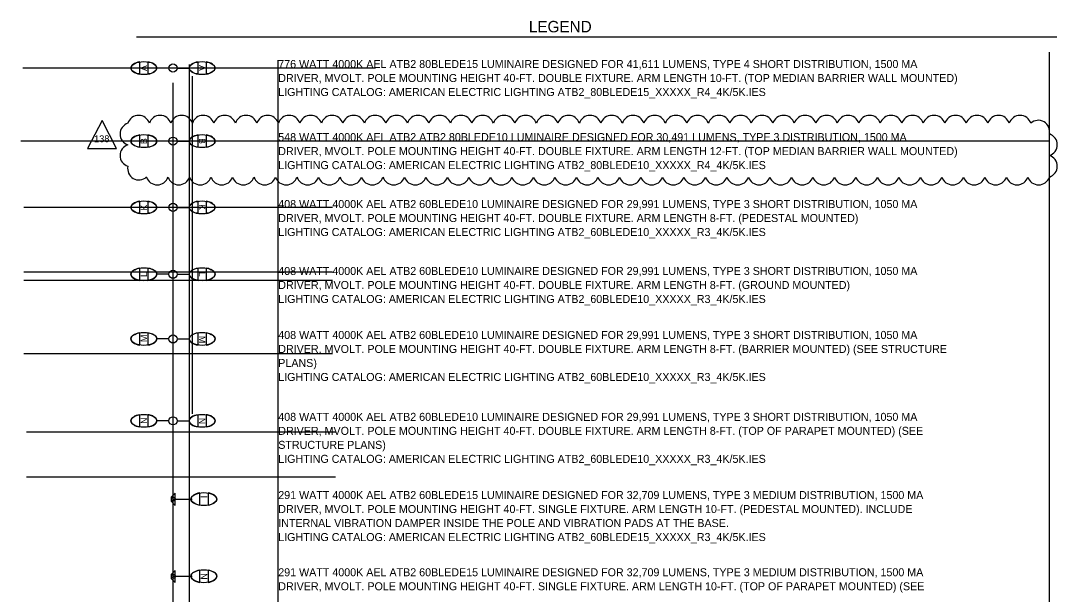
# Model space of a CAD drawing. Extents: x -0.6 to 15.1, y -0.9 to 9.2.
# Drawn here: x 0.27 to 9.34, y 4.17 to 9.19 of the extents above; entities that cross this region are included whole.
import ezdxf

# ---------------------------------------------------------------- set-up
doc = ezdxf.new("R2010")
doc.units = 0
for name, color, linetype in [('ActivePointCell_dp', 7, 'Continuous'), ('Cloud_dp', 7, 'Continuous'), ('PoleLight', 7, 'Continuous'), ('TextLabel', 7, 'Continuous'), ('TextMisc', 7, 'Continuous')]:
    doc.layers.add(name, color=color, linetype=linetype)

msp = doc.modelspace()

# ---------------------------------------------------------------- linework, layer by layer
at = {"layer": 'ActivePointCell_dp'}
for p, q in [((9.2686, -0.1347), (9.2686, 8.9112)), ((1.7419, 8.8041), (1.7419, 0.0422)), ((2.5213, -0.1347), (2.5213, 8.8406)), ((3.3736, 8.7727), (0.2875, 8.7727)), ((1.6003, 8.6424), (1.6003, 0.0422)), ((1.7686, 8.7005), (1.7686, 5.7492)), ((9.2686, 8.1335), (0.268, 8.1335)), ((2.9972, 7.554), (0.2951, 7.554)), ((2.9972, 6.9883), (0.2951, 6.9883)), ((2.9972, 6.913), (0.2951, 6.913)), ((2.9972, 6.272), (0.2951, 6.272)), ((3.0219, 5.588), (0.3198, 5.588)), ((3.0219, 5.1954), (0.3198, 5.1954))]:
    msp.add_line(p, q, dxfattribs=at)
at = {"layer": 'Cloud_dp'}
msp.add_lwpolyline([(0.98, 8.3128), (0.8533, 8.0688), (1.1068, 8.0688)], close=True, dxfattribs=at)
for centre, radius, start, end in [((1.2998, 8.2598), 0.0986, 17.5, 162.5), ((1.4878, 8.2598), 0.0986, 17.5, 162.5), ((1.6759, 8.2598), 0.0986, 17.5, 162.5), ((1.864, 8.2598), 0.0986, 17.5, 162.5), ((2.0521, 8.2598), 0.0986, 17.5, 162.5), ((2.2402, 8.2598), 0.0986, 17.5, 162.5), ((2.4283, 8.2598), 0.0986, 17.5, 162.5), ((2.6164, 8.2598), 0.0986, 17.5, 162.5), ((2.8045, 8.2598), 0.0986, 17.5, 162.5), ((2.9926, 8.2598), 0.0986, 17.5, 162.5), ((3.1807, 8.2598), 0.0986, 17.5, 162.5), ((3.3688, 8.2598), 0.0986, 17.5, 162.5), ((3.5569, 8.2598), 0.0986, 17.5, 162.5), ((3.745, 8.2598), 0.0986, 17.5, 162.5), ((3.9331, 8.2598), 0.0986, 17.5, 162.5), ((4.1212, 8.2598), 0.0986, 17.5, 162.5), ((4.3093, 8.2598), 0.0986, 17.5, 162.5), ((4.4974, 8.2598), 0.0986, 17.5, 162.5), ((4.6855, 8.2598), 0.0986, 17.5, 162.5), ((4.8736, 8.2598), 0.0986, 17.5, 162.5), ((5.0616, 8.2598), 0.0986, 17.5, 162.5), ((5.2497, 8.2598), 0.0986, 17.5, 162.5), ((5.4378, 8.2598), 0.0986, 17.5, 162.5), ((5.6259, 8.2598), 0.0986, 17.5, 162.5), ((5.814, 8.2598), 0.0986, 17.5, 162.5), ((6.0021, 8.2598), 0.0986, 17.5, 162.5), ((6.1902, 8.2598), 0.0986, 17.5, 162.5), ((6.3783, 8.2598), 0.0986, 17.5, 162.5), ((6.5664, 8.2598), 0.0986, 17.5, 162.5), ((6.7545, 8.2598), 0.0986, 17.5, 162.5), ((6.9426, 8.2598), 0.0986, 17.5, 162.5), ((7.1307, 8.2598), 0.0986, 17.5, 162.5), ((7.3188, 8.2598), 0.0986, 17.5, 162.5), ((7.5069, 8.2598), 0.0986, 17.5, 162.5), ((7.695, 8.2598), 0.0986, 17.5, 162.5), ((7.8831, 8.2598), 0.0986, 17.5, 162.5), ((8.0712, 8.2598), 0.0986, 17.5, 162.5), ((8.2593, 8.2598), 0.0986, 17.5, 162.5), ((8.4473, 8.2598), 0.0986, 17.5, 162.5), ((8.6354, 8.2598), 0.0986, 17.5, 162.5), ((8.8235, 8.2598), 0.0986, 17.5, 162.5), ((9.0116, 8.2598), 0.0986, 17.5, 162.5), ((1.2354, 8.1954), 0.0986, 107.5, 252.5), ((9.1723, 8.2169), 0.0985, 347.55602, 132.55602), ((9.2389, 8.1016), 0.0986, 287.5, 72.5), ((1.2354, 8.0074), 0.0986, 107.5, 252.5), ((9.2389, 7.9135), 0.0986, 287.5, 72.5), ((1.3019, 7.8921), 0.0985, 167.55602, 312.55602), ((1.4626, 7.8491), 0.0986, 197.5, 342.5), ((1.6507, 7.8491), 0.0986, 197.5, 342.5), ((1.8388, 7.8491), 0.0986, 197.5, 342.5), ((2.0269, 7.8491), 0.0986, 197.5, 342.5), ((2.215, 7.8491), 0.0986, 197.5, 342.5), ((2.4031, 7.8491), 0.0986, 197.5, 342.5), ((2.5912, 7.8491), 0.0986, 197.5, 342.5), ((2.7793, 7.8491), 0.0986, 197.5, 342.5), ((2.9674, 7.8491), 0.0986, 197.5, 342.5), ((3.1555, 7.8491), 0.0986, 197.5, 342.5), ((3.3436, 7.8491), 0.0986, 197.5, 342.5), ((3.5317, 7.8491), 0.0986, 197.5, 342.5), ((3.7198, 7.8491), 0.0986, 197.5, 342.5), ((3.9079, 7.8491), 0.0986, 197.5, 342.5), ((4.096, 7.8491), 0.0986, 197.5, 342.5), ((4.2841, 7.8491), 0.0986, 197.5, 342.5), ((4.4721, 7.8491), 0.0986, 197.5, 342.5), ((4.6602, 7.8491), 0.0986, 197.5, 342.5), ((4.8483, 7.8491), 0.0986, 197.5, 342.5), ((5.0364, 7.8491), 0.0986, 197.5, 342.5), ((5.2245, 7.8491), 0.0986, 197.5, 342.5), ((5.4126, 7.8491), 0.0986, 197.5, 342.5), ((5.6007, 7.8491), 0.0986, 197.5, 342.5), ((5.7888, 7.8491), 0.0986, 197.5, 342.5), ((5.9769, 7.8491), 0.0986, 197.5, 342.5), ((6.165, 7.8491), 0.0986, 197.5, 342.5), ((6.3531, 7.8491), 0.0986, 197.5, 342.5), ((6.5412, 7.8491), 0.0986, 197.5, 342.5), ((6.7293, 7.8491), 0.0986, 197.5, 342.5), ((6.9174, 7.8491), 0.0986, 197.5, 342.5), ((7.1055, 7.8491), 0.0986, 197.5, 342.5), ((7.2936, 7.8491), 0.0986, 197.5, 342.5), ((7.4817, 7.8491), 0.0986, 197.5, 342.5), ((7.6698, 7.8491), 0.0986, 197.5, 342.5), ((7.8579, 7.8491), 0.0986, 197.5, 342.5), ((8.0459, 7.8491), 0.0986, 197.5, 342.5), ((8.234, 7.8491), 0.0986, 197.5, 342.5), ((8.4221, 7.8491), 0.0986, 197.5, 342.5), ((8.6102, 7.8491), 0.0986, 197.5, 342.5), ((8.7983, 7.8491), 0.0986, 197.5, 342.5), ((8.9864, 7.8491), 0.0986, 197.5, 342.5), ((9.1745, 7.8491), 0.0986, 197.5, 342.5)]:
    msp.add_arc(centre, radius, start, end, dxfattribs=at)
at = {"layer": 'PoleLight'}
for p, q in [((1.3097, 8.719), (1.3097, 8.8264)), ((1.3812, 8.8264), (1.3812, 8.719)), ((1.8194, 8.719), (1.8194, 8.8264)), ((1.8909, 8.8264), (1.8909, 8.719)), ((1.5649, 8.7727), (1.4587, 8.7727)), ((1.6357, 8.7727), (1.7419, 8.7727)), ((1.3097, 8.0797), (1.3097, 8.1872)), ((1.3812, 8.1872), (1.3812, 8.0797)), ((1.8194, 8.0797), (1.8194, 8.1872)), ((1.8909, 8.1872), (1.8909, 8.0797)), ((1.5649, 8.1335), (1.4587, 8.1335)), ((1.6357, 8.1335), (1.7419, 8.1335)), ((1.3097, 7.5003), (1.3097, 7.6078)), ((1.3812, 7.6078), (1.3812, 7.5003)), ((1.5649, 7.554), (1.4587, 7.554)), ((1.6357, 7.554), (1.7419, 7.554)), ((1.8194, 7.5003), (1.8194, 7.6078)), ((1.8909, 7.6078), (1.8909, 7.5003)), ((1.3097, 6.9149), (1.3097, 7.0224)), ((1.3812, 7.0224), (1.3812, 6.9149)), ((1.8194, 6.9149), (1.8194, 7.0224)), ((1.8909, 7.0224), (1.8909, 6.9149)), ((1.5649, 6.9686), (1.4587, 6.9686)), ((1.6357, 6.9686), (1.7419, 6.9686)), ((1.3097, 6.3491), (1.3097, 6.4566)), ((1.3812, 6.4566), (1.3812, 6.3491)), ((1.8194, 6.3491), (1.8194, 6.4566)), ((1.8909, 6.4566), (1.8909, 6.3491)), ((1.5649, 6.4029), (1.4587, 6.4029)), ((1.6357, 6.4029), (1.7419, 6.4029)), ((1.3097, 5.6329), (1.3097, 5.7404)), ((1.3812, 5.7404), (1.3812, 5.6329)), ((1.8194, 5.6329), (1.8194, 5.7404)), ((1.8909, 5.7404), (1.8909, 5.6329)), ((1.5649, 5.6866), (1.4587, 5.6866)), ((1.6357, 5.6866), (1.7419, 5.6866)), ((1.6003, 5.0026), (1.7693, 5.0026)), ((1.8352, 4.9489), (1.8352, 5.0564)), ((1.9067, 5.0564), (1.9067, 4.9489)), ((1.8352, 4.2734), (1.8352, 4.3809)), ((1.9067, 4.3809), (1.9067, 4.2734)), ((1.6003, 4.3271), (1.7693, 4.3271))]:
    msp.add_line(p, q, dxfattribs=at)
for points in [[(1.5845, 5.0185), (1.5846, 4.9828), (1.6202, 4.947), (1.6202, 5.0543)], [(1.5845, 4.3431), (1.5846, 4.3073), (1.6202, 4.2716), (1.6202, 4.3788)]]:
    msp.add_lwpolyline(points, close=True, dxfattribs=at)
for centre, radius in [((1.6003, 8.7727), 0.0354), ((1.6003, 8.7727), 0.0354), ((1.6003, 8.1335), 0.0354), ((1.6003, 8.1335), 0.0354), ((1.6003, 7.554), 0.0354), ((1.6003, 7.554), 0.0354), ((1.6003, 6.9686), 0.0354), ((1.6003, 6.9686), 0.0354), ((1.6003, 6.4029), 0.0354), ((1.6003, 6.4029), 0.0354), ((1.6003, 5.6866), 0.0354), ((1.6003, 5.6866), 0.0354), ((1.6036, 5.0024), 0.0163), ((1.6036, 4.3269), 0.0163)]:
    msp.add_circle(centre, radius, dxfattribs=at)
for centre, major_axis in [((1.3455, 8.7727), (0.1133, 0)), ((1.8551, 8.7727), (0.1133, 0)), ((1.3455, 8.1335), (0.1133, 0)), ((1.8551, 8.1335), (0.1133, 0)), ((1.3455, 7.554), (0.1133, 0)), ((1.8551, 7.554), (0.1133, 0)), ((1.3455, 6.9686), (0.1133, 0)), ((1.8551, 6.9686), (0.1133, 0)), ((1.3455, 6.4029), (0.1133, 0)), ((1.8551, 6.4029), (0.1133, 0)), ((1.3455, 5.6866), (0.1133, 0)), ((1.8551, 5.6866), (0.1133, 0)), ((1.8709, 5.0026), (-0.1133, 0)), ((1.8709, 4.3271), (-0.1133, 0))]:
    msp.add_ellipse(centre, major_axis=major_axis, ratio=0.5, dxfattribs=at)
for centre, major_axis, start_param, end_param in [((1.3455, 8.7727), (0.1133, 0), 1.891945, 4.391241), ((1.3455, 8.7727), (0.1133, 0), 0.847605, 1.249648), ((1.3455, 8.7727), (0.1133, 0), 0, 0.847605), ((1.8551, 8.7727), (0.1133, 0), 1.891945, 4.391241), ((1.8551, 8.7727), (0.1133, 0), 0.847605, 1.249648), ((1.8551, 8.7727), (0.1133, 0), 0, 0.847605), ((1.3455, 8.7727), (0.1133, 0), 5.033538, 6.283185), ((1.8551, 8.7727), (0.1133, 0), 5.033538, 6.283185), ((1.3455, 8.1335), (0.1133, 0), 1.891945, 4.391241), ((1.3455, 8.1335), (0.1133, 0), 0.847605, 1.249648), ((1.3455, 8.1335), (0.1133, 0), 0, 0.847605), ((1.8551, 8.1335), (0.1133, 0), 1.891945, 4.391241), ((1.8551, 8.1335), (0.1133, 0), 0.847605, 1.249648), ((1.8551, 8.1335), (0.1133, 0), 0, 0.847605), ((1.3455, 8.1335), (0.1133, 0), 5.033538, 6.283185), ((1.8551, 8.1335), (0.1133, 0), 5.033538, 6.283185), ((1.3455, 7.554), (0.1133, 0), 1.891945, 4.391241), ((1.3455, 7.554), (0.1133, 0), 0.847605, 1.249648), ((1.3455, 7.554), (0.1133, 0), 5.033538, 6.283185), ((1.3455, 7.554), (0.1133, 0), 0, 0.847605), ((1.8551, 7.554), (0.1133, 0), 1.891945, 4.391241), ((1.8551, 7.554), (0.1133, 0), 0.847605, 1.249648), ((1.8551, 7.554), (0.1133, 0), 5.033538, 6.283185), ((1.8551, 7.554), (0.1133, 0), 0, 0.847605), ((1.3455, 6.9686), (0.1133, 0), 1.891945, 4.391241), ((1.3455, 6.9686), (0.1133, 0), 0.847605, 1.249648), ((1.3455, 6.9686), (0.1133, 0), 0, 0.847605), ((1.8551, 6.9686), (0.1133, 0), 1.891945, 4.391241), ((1.8551, 6.9686), (0.1133, 0), 0.847605, 1.249648), ((1.8551, 6.9686), (0.1133, 0), 0, 0.847605), ((1.3455, 6.9686), (0.1133, 0), 5.033538, 6.283185), ((1.8551, 6.9686), (0.1133, 0), 5.033538, 6.283185), ((1.3455, 6.4029), (0.1133, 0), 1.891945, 4.391241), ((1.3455, 6.4029), (0.1133, 0), 0.847605, 1.249648), ((1.3455, 6.4029), (0.1133, 0), 0, 0.847605), ((1.8551, 6.4029), (0.1133, 0), 1.891945, 4.391241), ((1.8551, 6.4029), (0.1133, 0), 0.847605, 1.249648), ((1.8551, 6.4029), (0.1133, 0), 0, 0.847605), ((1.3455, 6.4029), (0.1133, 0), 5.033538, 6.283185), ((1.8551, 6.4029), (0.1133, 0), 5.033538, 6.283185), ((1.3455, 5.6866), (0.1133, 0), 1.891945, 4.391241), ((1.3455, 5.6866), (0.1133, 0), 0.847605, 1.249648), ((1.3455, 5.6866), (0.1133, 0), 0, 0.847605), ((1.8551, 5.6866), (0.1133, 0), 1.891945, 4.391241), ((1.8551, 5.6866), (0.1133, 0), 0.847605, 1.249648), ((1.8551, 5.6866), (0.1133, 0), 0, 0.847605), ((1.3455, 5.6866), (0.1133, 0), 5.033538, 6.283185), ((1.8551, 5.6866), (0.1133, 0), 5.033538, 6.283185), ((1.8709, 5.0026), (-0.1133, 0), 5.033538, 6.283185), ((1.8709, 5.0026), (-0.1133, 0), 0, 0.847605), ((1.8709, 5.0026), (-0.1133, 0), 1.891945, 4.391241), ((1.8709, 5.0026), (-0.1133, 0), 0.847605, 1.249648), ((1.8709, 4.3271), (-0.1133, 0), 5.033538, 6.283185), ((1.8709, 4.3271), (-0.1133, 0), 1.891945, 4.391241), ((1.8709, 4.3271), (-0.1133, 0), 0, 0.847605), ((1.8709, 4.3271), (-0.1133, 0), 0.847605, 1.249648)]:
    msp.add_ellipse(centre, major_axis=major_axis, ratio=0.5, start_param=start_param, end_param=end_param, dxfattribs=at)
at = {"layer": 'TextLabel'}
msp.add_line((1.2805, 9.0443), (9.3344, 9.0443), dxfattribs=at)

# ---------------------------------------------------------------- texts
at = {"layer": 'Cloud_dp'}
msp.add_text('138', height=0.05998, rotation=0, dxfattribs=at).set_placement((0.9101, 8.1238))
at = {"layer": 'TextLabel'}
for s, rotation, p in [('A', 270, (1.8265, 8.7993)), ('A', 90, (1.3741, 8.746)), ('B', 90, (1.3741, 8.1073)), ('B', 270, (1.8265, 8.1596)), ('K', 90, (1.3741, 7.5269)), ('K', 270, (1.8265, 7.5812)), ('L', 90, (1.3741, 6.9458)), ('L', 270, (1.8265, 6.9915)), ('M', 90, (1.3741, 6.3764)), ('M', 270, (1.8265, 6.4293)), ('N', 90, (1.3741, 5.6603)), ('N', 270, (1.8265, 5.7129)), ('I', 270.00003, (1.8427, 5.0319)), ('N', 270.00003, (1.8423, 4.3534))]:
    msp.add_text(s, height=0.0572, rotation=rotation, dxfattribs=at).set_placement(p)
at = {"layer": 'TextMisc'}
for s, height, p in [('LEGEND', 0.1, (4.7139, 9.0848)), ('776 WATT 4000K AEL ATB2 80BLEDE15 LUMINAIRE DESIGNED FOR 41,611 LUMENS, TYPE 4 SHORT DISTRIBUTION, 1500 MA ', 0.07, (2.5213, 8.7727)), ('DRIVER, MVOLT. POLE MOUNTING HEIGHT 40-FT. DOUBLE FIXTURE. ARM LENGTH 10-FT. (TOP MEDIAN BARRIER WALL MOUNTED)', 0.07, (2.5213, 8.6502)), ('LIGHTING CATALOG: AMERICAN ELECTRIC LIGHTING ATB2_80BLEDE15_XXXXX_R4_4K/5K.IES', 0.07, (2.5213, 8.5277)), ('548 WATT 4000K AEL ATB2 ATB2 80BLEDE10 LUMINAIRE DESIGNED FOR 30,491 LUMENS, TYPE 3 DISTRIBUTION, 1500 MA ', 0.07, (2.5213, 8.1335)), ('DRIVER, MVOLT. POLE MOUNTING HEIGHT 40-FT. DOUBLE FIXTURE. ARM LENGTH 12-FT. (TOP MEDIAN BARRIER WALL MOUNTED)', 0.07, (2.5213, 8.011)), ('LIGHTING CATALOG: AMERICAN ELECTRIC LIGHTING ATB2_80BLEDE10_XXXXX_R4_4K/5K.IES', 0.07, (2.5213, 7.8885)), ('408 WATT 4000K AEL ATB2 60BLEDE10 LUMINAIRE DESIGNED FOR 29,991 LUMENS, TYPE 3 SHORT DISTRIBUTION, 1050 MA ', 0.07, (2.5213, 7.548)), ('DRIVER, MVOLT. POLE MOUNTING HEIGHT 40-FT. DOUBLE FIXTURE. ARM LENGTH 8-FT. (PEDESTAL MOUNTED)', 0.07, (2.5213, 7.4255)), ('LIGHTING CATALOG: AMERICAN ELECTRIC LIGHTING ATB2_60BLEDE10_XXXXX_R3_4K/5K.IES', 0.07, (2.5213, 7.303)), ('408 WATT 4000K AEL ATB2 60BLEDE10 LUMINAIRE DESIGNED FOR 29,991 LUMENS, TYPE 3 SHORT DISTRIBUTION, 1050 MA ', 0.07, (2.5213, 6.9626)), ('DRIVER, MVOLT. POLE MOUNTING HEIGHT 40-FT. DOUBLE FIXTURE. ARM LENGTH 8-FT. (GROUND MOUNTED)', 0.07, (2.5213, 6.8401)), ('LIGHTING CATALOG: AMERICAN ELECTRIC LIGHTING ATB2_60BLEDE10_XXXXX_R3_4K/5K.IES', 0.07, (2.5213, 6.7176)), ('408 WATT 4000K AEL ATB2 60BLEDE10 LUMINAIRE DESIGNED FOR 29,991 LUMENS, TYPE 3 SHORT DISTRIBUTION, 1050 MA ', 0.07, (2.5213, 6.4029)), ('DRIVER, MVOLT. POLE MOUNTING HEIGHT 40-FT. DOUBLE FIXTURE. ARM LENGTH 8-FT. (BARRIER MOUNTED) (SEE STRUCTURE ', 0.07, (2.5213, 6.2804)), ('PLANS)', 0.07, (2.5213, 6.1579)), ('LIGHTING CATALOG: AMERICAN ELECTRIC LIGHTING ATB2_60BLEDE10_XXXXX_R3_4K/5K.IES', 0.07, (2.5213, 6.0354)), ('408 WATT 4000K AEL ATB2 60BLEDE10 LUMINAIRE DESIGNED FOR 29,991 LUMENS, TYPE 3 SHORT DISTRIBUTION, 1050 MA ', 0.07, (2.5213, 5.6866)), ('DRIVER, MVOLT. POLE MOUNTING HEIGHT 40-FT. DOUBLE FIXTURE. ARM LENGTH 8-FT. (TOP OF PARAPET MOUNTED) (SEE ', 0.07, (2.5213, 5.5641)), ('STRUCTURE PLANS)', 0.07, (2.5213, 5.4416)), ('LIGHTING CATALOG: AMERICAN ELECTRIC LIGHTING ATB2_60BLEDE10_XXXXX_R3_4K/5K.IES', 0.07, (2.5213, 5.3191)), ('291 WATT 4000K AEL ATB2 60BLEDE15 LUMINAIRE DESIGNED FOR 32,709 LUMENS, TYPE 3 MEDIUM DISTRIBUTION, 1500 MA ', 0.07, (2.5213, 5.0026)), ('DRIVER, MVOLT. POLE MOUNTING HEIGHT 40-FT. SINGLE FIXTURE. ARM LENGTH 10-FT. (PEDESTAL MOUNTED). INCLUDE ', 0.07, (2.5213, 4.8801)), ('INTERNAL VIBRATION DAMPER INSIDE THE POLE AND VIBRATION PADS AT THE BASE.', 0.07, (2.5213, 4.7576)), ('LIGHTING CATALOG: AMERICAN ELECTRIC LIGHTING ATB2_60BLEDE15_XXXXX_R3_4K/5K.IES', 0.07, (2.5213, 4.6351)), ('291 WATT 4000K AEL ATB2 60BLEDE15 LUMINAIRE DESIGNED FOR 32,709 LUMENS, TYPE 3 MEDIUM DISTRIBUTION, 1500 MA ', 0.07, (2.5213, 4.3271)), ('DRIVER, MVOLT. POLE MOUNTING HEIGHT 40-FT. SINGLE FIXTURE. ARM LENGTH 10-FT. (TOP OF PARAPET MOUNTED) (SEE ', 0.07, (2.5213, 4.2046))]:
    msp.add_text(s, height=height, dxfattribs=at).set_placement(p)

doc.saveas('drawing.dxf')
